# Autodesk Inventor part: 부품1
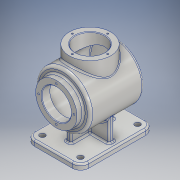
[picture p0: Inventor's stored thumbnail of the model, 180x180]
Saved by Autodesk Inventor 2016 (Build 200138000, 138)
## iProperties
Created: 2016-09
Part Number: 부품1
Material: 알루미늄 6061
Document SubType Name: Modeling
Designer: Administrator
Density: 2.7 g/cm^3
Appearance: 알루미늄 - 평지
Mass: 966.15 g
Surface Area: 1281.46 cm^2
Volume: 357.833 cm^3
Author: Administrator
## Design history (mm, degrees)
sketch "스케치1"
  geometry: L1 (-50, 0)-(60, 0); L2 (-50, 0)-(-50, 50); L3 (-50, 50)-(48.562, 50); A1 r 115 centre (-55, 0) between (60, 0) and (48.562, 50); 1 further point
  constraints: 6 end point, 2 point on circle, 1 centre point, 1 horizontal, 1 horizontal alignment, 1 perpendicular, 1 point on line, 1 vertical
  dimensions: "d0" = 110 distance of L1.start L1.end; "d1" = 115 radius of A1; "d2" = 100 diameter of L3 L1; "d3" = 50 distance of point (0, 0) L1.start
revolve "회전1" sketch "스케치1" stored, may be unused: angle "d4" = 90 deg
feature "쉘1" dims "d5" = 3
node "작업 평면1"
sketch "스케치3"
  geometry: L1 (67.5, -50)-(-67.5, -50); L2 (-67.5, -50)-(-67.5, 50); L3 (-67.5, 50)-(67.5, 50); L4 (67.5, 50)-(67.5, -50); L5 (67.5, -50)-(-67.5, 50); L6 (-67.5, -50)-(67.5, 50); 1 further point
  constraints: 12 end point, 2 midpoint, 2 parallel, 1 horizontal, 1 perpendicular
  dimensions: "d7" = 135 distance of L1.start L1.end; "d8" = 100 distance of L1.end L2.end
extrude "돌출1" join sketch "스케치3" distance "d9" = 10; taper "d10" = 0 deg
sketch "스케치4"
  geometry: L1 (-67.5, 50)-(67.5, 50) reference; L2 (67.5, 50)-(67.5, -50) reference; L3 (67.5, -50)-(-67.5, -50) reference; L4 (-67.5, -50)-(-67.5, 50) reference; L5 (67.5, 50)-(67.5, -50) reference; L6 (67.5, -50)-(-67.5, -50) reference; L7 (-67.5, -50)-(-67.5, 50) reference; L8 (-67.5, 50)-(67.5, 50) reference; L9 (-67.5, -50)-(-67.5, 50) reference; L10 (-67.5, 0)-(67.5, 0); L11 (-67.5, 50)-(67.5, 50) reference; L12 (0, 50)-(0, -50); L13 (67.5, -50)-(-67.5, -50) reference; L14 (-40, 5)-(40, 5); L15 (40, 5)-(40, -5); L16 (40, -5)-(-40, -5); L17 (-40, -5)-(-40, 5); L18 (-40, 5)-(40, -5); L19 (40, 5)-(-40, -5); 1 further point
  constraints: 16 end point, 7 midpoint, 2 parallel, 1 horizontal, 1 perpendicular
  dimensions: "d14" = 10 distance of L14.end L15.end; "d16" = 40 distance from line of L17 point (0, 0)
extrude "돌출2" join sketch "스케치4" stored distance "d17" = 10; taper "d18" = 0 deg
sketch "스케치5"
  geometry: L1 (-72, 50)-(-72, -50) reference; L2 (-82, -50)-(-72, -50) reference; L3 (-30, -40)-(-72, -40); 2 further points
  constraints: 2 end point, 1 point on line, 2 other
  dimensions: "d19" = 90 deg angle of L1 L3; "d20" = 40 vertical distance of L3.end point (0, 0)
feature "리브1" sketch "스케치5" dims "d21" = 1, "d22" = 10, "d23" = 0, "d24" = 0, "d25" = 1, "d26" = 1
node "작업 평면3"
sketch "스케치6"
  geometry: C1 r 38 at (0, 0); 1 further point
  constraints: 1 centre point, 1 coincident
  dimensions: "d28" = 76 diameter of C1
extrude "돌출3" join sketch "스케치6" stored distance "d29" = 10; taper "d30" = 0 deg
hole "구멍1" diameter "d33" = 54; stored, may be unused: countersink angle "d37" = 90 deg, drill point angle "d39" = 118 deg; dims "d31" = 10, "d32" = 10, "d34" = 6, "d35" = 4, "d36" = 2, "d38" = 8
sketch "스케치7"
  geometry: C1 r 50 at (0, 0) reference; C2 r 38 at (0, 0); 1 further point
  constraints: 1 centre point, 1 coincident
  dimensions: "d40" = 76 diameter of C2
extrude "돌출4" join sketch "스케치7" distance "d41" = 12; taper "d42" = 0 deg
hole "구멍2" diameter "d45" = 54; stored, may be unused: countersink angle "d49" = 90 deg, drill point angle "d51" = 118 deg; dims "d43" = 10, "d44" = 10, "d46" = 6, "d47" = 4, "d48" = 2, "d50" = 15
fillet "모깎기1" dims "d52" = 3
fillet "모깎기2" dims "d53" = 3
fillet "모깎기3" dims "d54" = 5
fillet "모깎기4" dims "d55" = 3
fillet "모깎기5" dims "d56" = 15
fillet "모깎기6" dims "d57" = 3
chamfer "모따기1" distance "d58" = 1; stored, may be unused: second distance "d59" = 2, angle "d60" = 45 deg
fillet "모깎기7" dims "d61" = 2
sketch "스케치8"
  geometry: L1 (67.5, 35)-(67.5, -35) reference; L2 (52.5, -50)-(-52.5, -50) reference; L3 (-67.5, -35)-(-67.5, 35) reference; L4 (-52.5, 50)-(52.5, 50) reference; C1 r 5 at (-52.5, 35); C2 r 5 at (52.5, 35); C3 r 5 at (52.5, -35); C4 r 5 at (-52.5, -35); A1 r 15 centre (52.5, 35) between (67.5, 35) and (52.5, 50) reference; A2 r 15 centre (52.5, -35) between (52.5, -50) and (67.5, -35) reference; A3 r 15 centre (-52.5, -35) between (-67.5, -35) and (-52.5, -50) reference; A4 r 15 centre (-52.5, 35) between (-52.5, 50) and (-67.5, 35) reference; A5 r 15 centre (52.5, 35) between (67.5, 35) and (52.5, 50) reference; 1 further point
  constraints: 4 centre point, 4 coincident, 3 equal radius
  dimensions: "d62" = 10 diameter of C1
extrude "돌출6" cut sketch "스케치8" stored distance "d65" = 12; taper "d66" = 0 deg
sketch "스케치9" dims "d67" = 65
  geometry: 3 further points
  constraints: 2 vertical alignment, 1 coincident, 2 other
hole "구멍3" sketch "스케치9" at (0, 32.5) diameter "d68" = 3.242; stored, may be unused: countersink angle "d72" = 90 deg, drill point angle "d74" = 118 deg; dims "d69" = 8, "d70" = 4, "d71" = 2, "d73" = 10
sketch "스케치10" dims "d78" = 65
  geometry: 3 further points
  constraints: 2 vertical alignment, 1 coincident, 2 other
hole "구멍4" sketch "스케치10" at (0, 32.5) diameter "d79" = 3.242; stored, may be unused: countersink angle "d83" = 90 deg, drill point angle "d85" = 118 deg; dims "d80" = 8, "d81" = 4, "d82" = 2, "d84" = 10
node "작업 평면4"
sketch "스케치11"
  geometry: 2 further points
  constraints: 1 coincident, 1 other
feature "엠보싱1" sketch "스케치11" dims "d0" = 110, "d1" = 115, "d2" = 100, "d3" = 50, "d90" = 0.5, "d91" = 0
node "솔리드1"
mirror "대칭1"
pattern_circular "원형 패턴1" dims angle "d76" = 360 deg
pattern_circular "원형 패턴2" dims angle "d87" = 360 deg
node "투영된 루프1"
node "작업 평면2"
node "투영된 루프2"
node "절단 모서리 투영1"
other parameters: "d6" = -82, "d27" = -147, "d89" = 98.425
